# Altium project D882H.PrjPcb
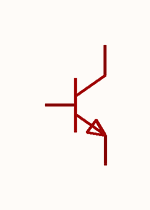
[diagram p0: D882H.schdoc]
1 sheet, 1 parts. Net scope: global (net labels, ports and power ports of the same name join across sheets).

## Sheet D882H.schdoc
size 127 x 101 mm

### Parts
Q?  d882h(range:160-320)  [SOT-89-3_L4.5-W2.5-P1.50-LS4.2-BR]  (value not drawn)

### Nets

Not connected (* = marked no-connect by the designer): Q? 1 2 3

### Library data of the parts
Q? = d882h(range:160-320): 晶体管类型:NPN;集电极电流(Ic):3A;集射极击穿电压(Vceo):70V;耗散功率(Pd):500mW;直流电流增益(hFE):60;; Manufacturer: CJ(江苏长电/长晶); AddInBom: yes; ModelId: 6db690b7897d4d18a30d90c1b89525ee; ModelName: SOT-89-3_L4.3-W2.5-H1.6-LS4.1-P1.50; ModelTransform: 161.417,169.291,0,180,0,0,-18.661,0,0; type: NPN; Current - Collector(Ic): 3A; Collector - Emitter Voltage VCEO: 70V; Pd - Power Dissipation: 500mW; DC Current Gain: 60; Transition frequency(fT): 50MHz; Current - Collector Cutoff: 1uA; Vce Saturation(VCE(sat)): 500mV; Emitter-Base Voltage(Vebo): 6V; Number: 1个NPN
